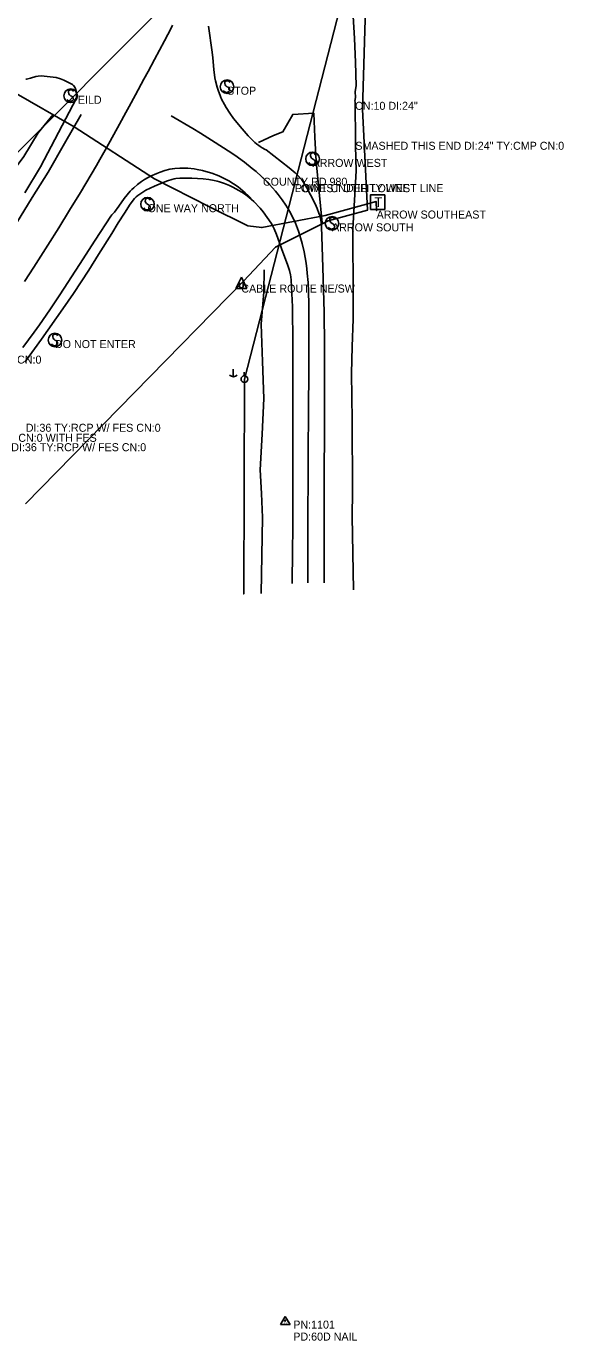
# Model space of a CAD drawing. Extents: x 1676038 to 1677961, y 226475 to 233854.
# Drawn here: x 1677207 to 1677543, y 227480 to 228301 of the extents above; entities that cross this region are included whole.
import ezdxf

# ---------------------------------------------------------------- set-up
doc = ezdxf.new("R2010")
doc.units = 0
for name, color, linetype in [('S_BASELINE', 7, 'Continuous'), ('S_CROSS_DRAIN_ANNOT', 7, 'Continuous'), ('S_DITCHLINE', 7, 'Continuous'), ('S_DRG_PT_SYM', 7, 'Continuous'), ('S_EDGE_PAVEMENT', 7, 'Continuous'), ('S_ELECTRIC_UTILITIES', 7, 'Continuous'), ('S_ELECTRIC_UTILITIES_ANNOT', 7, 'Continuous'), ('S_FIBER_OPTIC_CABLE', 7, 'Continuous'), ('S_FIBER_OPTIC_CABLE_ANNOT', 7, 'Continuous'), ('S_GRAVEL_ROAD', 7, 'Continuous'), ('S_MSC_PT_SYM', 7, 'Continuous'), ('S_PAVEMENT_CROWN', 7, 'Continuous'), ('S_SECONDARY_CTL', 7, 'Continuous'), ('S_SECONDARY_CTL_ANNOT', 7, 'Continuous'), ('S_SHOULDER', 7, 'Continuous'), ('S_SIDE_DRAIN', 7, 'Continuous'), ('S_SIDE_DRAIN_ANNOT', 7, 'Continuous'), ('S_SIGN', 7, 'Continuous'), ('S_SIGN_ANNOT', 7, 'Continuous'), ('S_SURVEY_TEXT_ANNOT', 7, 'Continuous'), ('S_TELEPHONE_UTILITIES', 7, 'Continuous'), ('S_UNDERGROUND_CABLE', 7, 'Continuous'), ('S_UTILITY_POLE', 7, 'Continuous'), ('S_UTILITY_POLE_ANNOT', 7, 'Continuous'), ('S_UTL_PT_SYM', 7, 'Continuous')]:
    doc.layers.add(name, color=color, linetype=linetype)

msp = doc.modelspace()

# ---------------------------------------------------------------- linework, layer by layer
at = {"layer": 'S_BASELINE'}
msp.add_line((1676625.89, 227646.73), (1677368.16, 228389.18), dxfattribs=at)
at = {"layer": 'S_DITCHLINE'}
for points in [[(1677412.24, 228254.17), (1677412.6, 228256.39), (1677412.47, 228260.11), (1677413, 228263.83), (1677412.54, 228278.59), (1677412.08, 228293.34), (1677411.18, 228307.32)], [(1677139.76, 228123.95), (1677153.43, 228142.29), (1677158.71, 228149.29), (1677171.09, 228169.75), (1677183.47, 228190.22), (1677194.37, 228204.93), (1677205.27, 228219.64), (1677214.14, 228234.4), (1677223.67, 228245.72)], [(1677411.34, 227948.81), (1677410.93, 227971.75), (1677410.52, 227994.7), (1677410.65, 228010.19), (1677410.77, 228025.67), (1677410.6, 228040.23), (1677410.43, 228054.8), (1677410.25, 228069.36), (1677410.08, 228083.92), (1677410.62, 228100.96), (1677411.16, 228118), (1677411.12, 228132.07), (1677411.08, 228146.13), (1677411.04, 228160.19), (1677411, 228174.26), (1677412.02, 228192.39), (1677413.03, 228210.53), (1677412.69, 228226.29), (1677412.54, 228228.6)], [(1677353.55, 227946.6), (1677353.97, 227970.29), (1677354.38, 227993.98), (1677353.74, 228008.93), (1677353.09, 228023.88), (1677354.22, 228046.14), (1677355.36, 228068.4), (1677354.45, 228091.59), (1677353.55, 228114.78), (1677355.39, 228135.08), (1677355.46, 228148.71)]]:
    msp.add_lwpolyline(points, dxfattribs=at)
at = {"layer": 'S_DRG_PT_SYM'}
for points in [[(1677412.36, 228253.75), (1677412.36, 228253.8), (1677412.36, 228253.75), (1677412.31, 228253.75), (1677412.36, 228253.75), (1677412.36, 228253.7), (1677412.36, 228253.75), (1677412.41, 228253.75)], [(1677412.53, 228228.77), (1677412.53, 228228.82), (1677412.53, 228228.77), (1677412.48, 228228.77), (1677412.53, 228228.77), (1677412.53, 228228.72), (1677412.53, 228228.77), (1677412.58, 228228.77)]]:
    msp.add_lwpolyline(points, dxfattribs=at)
at = {"layer": 'S_EDGE_PAVEMENT'}
for points in [[(1677393.01, 227953.24), (1677392.99, 227973.14), (1677393.01, 227986.86), (1677393.04, 228000.57), (1677393.07, 228014.29), (1677393.1, 228028), (1677393.16, 228041.08), (1677393.22, 228054.15), (1677393.28, 228067.22), (1677393.33, 228080.3), (1677393.16, 228101.3), (1677392.99, 228122.29), (1677392.57, 228136.22), (1677392.15, 228150.14), (1677391.79, 228163.04), (1677391.42, 228175.94), (1677391.24, 228178.28), (1677390.99, 228179.8), (1677390.25, 228182.79), (1677389.77, 228184.26), (1677388.64, 228187.15), (1677387.33, 228190), (1677384.48, 228195.62), (1677382.22, 228199.98), (1677381.02, 228202.09), (1677378.99, 228205.06), (1677376.64, 228207.74), (1677374.9, 228209.39), (1677371.13, 228212.53), (1677356.79, 228223.79), (1677356.22, 228224.05), (1677354.29, 228225.04), (1677353.07, 228225.78), (1677350.75, 228227.46), (1677349.65, 228228.37), (1677347.54, 228230.33), (1677345.53, 228232.42), (1677341.72, 228236.81), (1677336.42, 228243.33), (1677333.96, 228246.68), (1677331.69, 228250.16), (1677330.64, 228251.96), (1677328.85, 228255.49), (1677328.14, 228257.11), (1677327.27, 228259.3), (1677326.87, 228260.41), (1677326.06, 228262.94), (1677325.08, 228266.78), (1677324.71, 228268.72), (1677324.02, 228274.02), (1677323.4, 228281.16), (1677322.99, 228284.76), (1677320.78, 228300.93)], [(1677200.64, 228177.93), (1677210.53, 228193.87), (1677220.43, 228209.81), (1677230.72, 228227.78), (1677241.01, 228245.75)], [(1677204.51, 228100.23), (1677211.72, 228109.83), (1677215.01, 228114.43), (1677221.43, 228123.74), (1677227.68, 228133.17), (1677240.04, 228152.19), (1677249.84, 228167.22), (1677259.63, 228182.24), (1677260.35, 228183.07), (1677261.84, 228184.85), (1677264.58, 228188.49), (1677268.07, 228193.36), (1677269.86, 228195.7), (1677271.77, 228197.94), (1677272.79, 228199.01), (1677273.91, 228200.09), (1677276.31, 228202.13), (1677278.89, 228203.99), (1677280.68, 228205.14), (1677284.42, 228207.22), (1677288.37, 228209.05), (1677290.38, 228209.83), (1677293.46, 228210.84), (1677296.59, 228211.6), (1677298.18, 228211.89), (1677299.68, 228212.09), (1677302.7, 228212.33), (1677305.74, 228212.36), (1677307.76, 228212.26), (1677311.8, 228211.83), (1677313.55, 228211.55), (1677317.04, 228210.81), (1677320.46, 228209.87), (1677322.72, 228209.14), (1677327.14, 228207.42), (1677331.36, 228205.43), (1677333.41, 228204.32), (1677336.4, 228202.51), (1677339.26, 228200.52), (1677340.64, 228199.47), (1677343.56, 228196.97), (1677345.43, 228195.21), (1677349.05, 228191.52), (1677352.97, 228187.21), (1677354.84, 228184.98), (1677357.47, 228181.52), (1677359.81, 228177.9), (1677360.85, 228176.02), (1677361.69, 228174.31), (1677363.19, 228170.78), (1677367.12, 228159.82), (1677370.1, 228152.18), (1677371.35, 228148.32), (1677371.96, 228145.71), (1677372.17, 228144.39), (1677372.37, 228142.38), (1677373.23, 228125.66), (1677373.35, 228102.82), (1677373.48, 228079.98), (1677373.48, 228067.05), (1677373.48, 228054.12), (1677373.48, 228041.18), (1677373.48, 228028.25), (1677373.43, 228014.55), (1677373.39, 228000.85), (1677373.34, 227987.15), (1677373.29, 227973.45), (1677373.05, 227952.85)]]:
    msp.add_lwpolyline(points, dxfattribs=at)
at = {"layer": 'S_ELECTRIC_UTILITIES'}
for p, q in [((1677343.16, 228080.48), (1677425.49, 228399.8)), ((1677342.78, 227946.34), (1677343.16, 228080.48))]:
    msp.add_line(p, q, dxfattribs=at)
at = {"layer": 'S_FIBER_OPTIC_CABLE'}
for p, q in [((1677416.97, 228249.14), (1677419.05, 228321.79)), ((1677199.06, 228259.69), (1677236.65, 228238.11)), ((1677420.05, 228186.02), (1677416.97, 228249.14)), ((1677236.65, 228238.11), (1677286.95, 228205.7)), ((1677286.95, 228205.7), (1677321.23, 228188.13)), ((1677321.23, 228188.13), (1677345.29, 228176.33)), ((1677393.7, 228182.74), (1677425.52, 228191.41)), ((1677425.52, 228191.41), (1677425.83, 228185.81)), ((1677354.08, 228175.16), (1677393.7, 228182.74)), ((1677362.65, 228162.87), (1677395.47, 228179.35)), ((1677395.47, 228179.35), (1677420.05, 228186.02)), ((1677345.29, 228176.33), (1677354.08, 228175.16)), ((1677342.55, 228141.77), (1677362.65, 228162.87)), ((1677206.22, 228002.56), (1677342.55, 228141.77))]:
    msp.add_line(p, q, dxfattribs=at)
at = {"layer": 'S_GRAVEL_ROAD'}
msp.add_lwpolyline([(1677391.86, 228178.22), (1677389.92, 228197.38), (1677387.97, 228216.53), (1677387.22, 228231.6), (1677386.46, 228246.68), (1677373.41, 228245.91), (1677367.22, 228234.89), (1677361.37, 228232.62), (1677351.91, 228228.25)], dxfattribs=at)
at = {"layer": 'S_MSC_PT_SYM'}
for points in [[(1677354.75, 228206.33), (1677354.75, 228206.38), (1677354.75, 228206.33), (1677354.7, 228206.33), (1677354.75, 228206.33), (1677354.75, 228206.28), (1677354.75, 228206.33), (1677354.8, 228206.33)], [(1677374.72, 228202.29), (1677374.72, 228202.34), (1677374.72, 228202.29), (1677374.67, 228202.29), (1677374.72, 228202.29), (1677374.72, 228202.24), (1677374.72, 228202.29), (1677374.77, 228202.29)]]:
    msp.add_lwpolyline(points, dxfattribs=at)
at = {"layer": 'S_PAVEMENT_CROWN'}
for points in [[(1677205.64, 228141.43), (1677211.52, 228150.46), (1677220.23, 228164.08), (1677227.05, 228175.06), (1677233.86, 228186.03), (1677240.57, 228197.07), (1677247.35, 228208.36), (1677250.69, 228214.03), (1677252.78, 228217.67), (1677256.92, 228224.98), (1677265, 228239.68), (1677269, 228247.04), (1677270.99, 228250.71), (1677274.97, 228258.06), (1677280.3, 228267.86), (1677282.97, 228272.78), (1677287, 228280.19), (1677293.29, 228291.86), (1677295.33, 228295.75), (1677296.33, 228297.69), (1677298.28, 228301.57)], [(1677382.81, 227953.23), (1677382.74, 227973.42), (1677382.8, 227987.07), (1677382.87, 228000.72), (1677382.94, 228014.37), (1677383.01, 228028.03), (1677383.1, 228041.01), (1677383.19, 228053.99), (1677383.29, 228066.97), (1677383.38, 228079.96), (1677383.41, 228101.62), (1677383.44, 228123.28), (1677383.42, 228127.21), (1677383.25, 228135), (1677382.95, 228140.8), (1677382.48, 228146.58), (1677382.18, 228149.46), (1677381.72, 228152.98), (1677380.52, 228159.98), (1677379.34, 228165.18), (1677377.86, 228170.3), (1677377.01, 228172.83), (1677375.04, 228177.84), (1677373.54, 228181.1), (1677371.31, 228185.34), (1677370.1, 228187.4), (1677369.02, 228189.13), (1677366.71, 228192.52), (1677364.25, 228195.78), (1677362.53, 228197.9), (1677358.91, 228201.99), (1677357.28, 228203.69), (1677353.94, 228206.98), (1677350.46, 228210.13), (1677348.08, 228212.16), (1677343.18, 228216.04), (1677337.18, 228220.34), (1677333.09, 228223.09), (1677324.81, 228228.42), (1677315.63, 228234.2), (1677310.97, 228236.99), (1677297.32, 228244.96)]]:
    msp.add_lwpolyline(points, dxfattribs=at)
at = {"layer": 'S_SECONDARY_CTL'}
for p, q in [((1677368.72, 227494.85), (1677365.71, 227489.9)), ((1677365.71, 227489.9), (1677371.67, 227489.9)), ((1677368.72, 227494.85), (1677371.67, 227489.9))]:
    msp.add_line(p, q, dxfattribs=at)
for radius in [0.311, 0.183, 0.103]:
    msp.add_circle((1677368.72, 227492.24), radius, dxfattribs=at)
at = {"layer": 'S_SHOULDER'}
for points in [[(1677206.5, 228267.87), (1677206.98, 228267.95), (1677209.47, 228268.53), (1677212.66, 228269.48), (1677214.27, 228269.8), (1677216.11, 228269.91), (1677219.85, 228269.64), (1677223.57, 228269.19), (1677225.39, 228268.87), (1677228.09, 228268.14), (1677230.16, 228267.29), (1677234.08, 228265.32), (1677235.59, 228264.48), (1677236.26, 228263.96), (1677237.14, 228262.9), (1677237.6, 228261.94), (1677237.78, 228261.36), (1677238.01, 228260.36), (1677238.24, 228257.89), (1677238.29, 228255.7), (1677238.29, 228255.98), (1677238.29, 228256.03)], [(1677205.85, 228196.84), (1677215.64, 228213.05), (1677226.95, 228234.53), (1677238.26, 228256)], [(1677205.8, 228091.1), (1677216.32, 228105.47), (1677229.71, 228124.4), (1677236.26, 228133.97), (1677245.82, 228148.48), (1677252.02, 228158.3), (1677260.19, 228171.46), (1677264.29, 228178.03), (1677268.17, 228184.17), (1677268.6, 228184.84), (1677271.38, 228189.27), (1677272.87, 228191.4), (1677274.51, 228193.38), (1677275.4, 228194.29), (1677276.5, 228195.26), (1677278.91, 228196.97), (1677281.51, 228198.45), (1677287.02, 228201.04), (1677292.36, 228203.39), (1677295.05, 228204.41), (1677297.78, 228205.22), (1677299.17, 228205.53), (1677300.36, 228205.73), (1677302.79, 228205.99), (1677305.25, 228206.1), (1677310.22, 228206.01), (1677317.34, 228205.56), (1677320.86, 228205.13), (1677324.34, 228204.51), (1677326.07, 228204.11), (1677327.65, 228203.68), (1677330.78, 228202.66), (1677333.84, 228201.43), (1677335.84, 228200.5), (1677339.71, 228198.42), (1677342.61, 228196.59), (1677344.01, 228195.6), (1677346.07, 228194.04), (1677349.04, 228191.5)]]:
    msp.add_lwpolyline(points, dxfattribs=at)
at = {"layer": 'S_SIDE_DRAIN'}
msp.add_line((1677412.53, 228228.77), (1677412.36, 228253.75), dxfattribs=at)
at = {"layer": 'S_SIGN'}
for centre in [(1677234.55, 228257.53), (1677332.3, 228263.17), (1677385.77, 228218.09), (1677282.56, 228189.77), (1677397.95, 228177.81), (1677224.7, 228104.88)]:
    msp.add_circle(centre, 4.24, dxfattribs=at)
for centre, radius, start, end in [((1677234.67, 228259.69), 1.62, 16.52582, 156.89569), ((1677332.04, 228261.77), 2.17, 204.64102, 335.35898), ((1677333.46, 228265.42), 2.55, 167.11961, 241.98129), ((1677332.42, 228265.32), 1.62, 16.52582, 156.89569), ((1677331.6, 228260.89), 2.38, 358.65289, 73.70634), ((1677234.28, 228256.13), 2.17, 204.64102, 335.35898), ((1677235.71, 228259.79), 2.55, 167.11961, 241.98129), ((1677233.84, 228255.25), 2.38, 358.65289, 73.70634), ((1677386.94, 228220.35), 2.55, 167.11961, 241.98129), ((1677385.9, 228220.25), 1.62, 16.52582, 156.89569), ((1677385.51, 228216.69), 2.17, 204.64102, 335.35898), ((1677385.07, 228215.81), 2.38, 358.65289, 73.70634), ((1677282.3, 228188.37), 2.17, 204.64102, 335.35898), ((1677283.72, 228192.02), 2.55, 167.11961, 241.98129), ((1677282.68, 228191.92), 1.62, 16.52582, 156.89569), ((1677281.86, 228187.49), 2.38, 358.65289, 73.70634), ((1677399.12, 228180.06), 2.55, 167.11961, 241.98129), ((1677398.08, 228179.96), 1.62, 16.52582, 156.89569), ((1677397.69, 228176.41), 2.17, 204.64102, 335.35898), ((1677397.25, 228175.52), 2.38, 358.65289, 73.70634), ((1677225.87, 228107.14), 2.55, 167.11961, 241.98129), ((1677224.83, 228107.04), 1.62, 16.52582, 156.89569), ((1677224, 228102.6), 2.38, 358.65289, 73.70634), ((1677224.44, 228103.48), 2.17, 204.64102, 335.35898)]:
    msp.add_arc(centre, radius, start, end, dxfattribs=at)
at = {"layer": 'S_TELEPHONE_UTILITIES'}
msp.add_lwpolyline([(1677421.91, 228186.56), (1677421.91, 228195.56), (1677430.91, 228195.56), (1677430.91, 228186.56)], close=True, dxfattribs=at)
at = {"layer": 'S_UNDERGROUND_CABLE'}
for p, q in [((1677341.24, 228144.11), (1677337.71, 228137.02)), ((1677340.04, 228138.26), (1677340.04, 228140.7)), ((1677340.66, 228137.6), (1677340.04, 228138.26)), ((1677341.86, 228137.6), (1677340.66, 228137.6)), ((1677341.24, 228144.11), (1677344.73, 228137.02)), ((1677342.4, 228138.26), (1677341.86, 228137.6)), ((1677342.4, 228140.7), (1677342.4, 228138.26)), ((1677337.71, 228137.02), (1677344.73, 228137.02))]:
    msp.add_line(p, q, dxfattribs=at)
at = {"layer": 'S_UTILITY_POLE'}
for p, q in [((1677336.19, 228086.7), (1677336.19, 228081.97)), ((1677343.03, 228082.63), (1677343.03, 228084.74))]:
    msp.add_line(p, q, dxfattribs=at)
msp.add_circle((1677343.16, 228080.49), 2.13, dxfattribs=at)
msp.add_arc((1677336.25, 228085.4), 3.41, 226.39718, 313.60282, dxfattribs=at)
at = {"layer": 'S_UTL_PT_SYM'}
for points in [[(1677416.97, 228249.14), (1677416.97, 228249.19), (1677416.97, 228249.14), (1677416.92, 228249.14), (1677416.97, 228249.14), (1677416.97, 228249.09), (1677416.97, 228249.14), (1677417.02, 228249.14)], [(1677236.65, 228238.11), (1677236.65, 228238.16), (1677236.65, 228238.11), (1677236.6, 228238.11), (1677236.65, 228238.11), (1677236.65, 228238.06), (1677236.65, 228238.11), (1677236.7, 228238.11)], [(1677286.95, 228205.7), (1677286.95, 228205.75), (1677286.95, 228205.7), (1677286.9, 228205.7), (1677286.95, 228205.7), (1677286.95, 228205.65), (1677286.95, 228205.7), (1677287, 228205.7)], [(1677374.72, 228202.29), (1677374.72, 228202.34), (1677374.72, 228202.29), (1677374.67, 228202.29), (1677374.72, 228202.29), (1677374.72, 228202.24), (1677374.72, 228202.29), (1677374.77, 228202.29)], [(1677321.23, 228188.13), (1677321.23, 228188.18), (1677321.23, 228188.13), (1677321.18, 228188.13), (1677321.23, 228188.13), (1677321.23, 228188.08), (1677321.23, 228188.13), (1677321.28, 228188.13)], [(1677425.52, 228191.41), (1677425.52, 228191.46), (1677425.52, 228191.41), (1677425.47, 228191.41), (1677425.52, 228191.41), (1677425.52, 228191.36), (1677425.52, 228191.41), (1677425.57, 228191.41)], [(1677393.7, 228182.74), (1677393.7, 228182.79), (1677393.7, 228182.74), (1677393.65, 228182.74), (1677393.7, 228182.74), (1677393.7, 228182.69), (1677393.7, 228182.74), (1677393.75, 228182.74)], [(1677395.47, 228179.35), (1677395.47, 228179.4), (1677395.47, 228179.35), (1677395.42, 228179.35), (1677395.47, 228179.35), (1677395.47, 228179.3), (1677395.47, 228179.35), (1677395.52, 228179.35)], [(1677420.05, 228186.02), (1677420.05, 228186.07), (1677420.05, 228186.02), (1677420, 228186.02), (1677420.05, 228186.02), (1677420.05, 228185.97), (1677420.05, 228186.02), (1677420.1, 228186.02)], [(1677425.83, 228185.81), (1677425.83, 228185.86), (1677425.83, 228185.81), (1677425.78, 228185.81), (1677425.83, 228185.81), (1677425.83, 228185.76), (1677425.83, 228185.81), (1677425.88, 228185.81)], [(1677345.29, 228176.33), (1677345.29, 228176.38), (1677345.29, 228176.33), (1677345.24, 228176.33), (1677345.29, 228176.33), (1677345.29, 228176.28), (1677345.29, 228176.33), (1677345.34, 228176.33)], [(1677354.08, 228175.16), (1677354.08, 228175.21), (1677354.08, 228175.16), (1677354.03, 228175.16), (1677354.08, 228175.16), (1677354.08, 228175.11), (1677354.08, 228175.16), (1677354.13, 228175.16)], [(1677362.65, 228162.87), (1677362.65, 228162.92), (1677362.65, 228162.87), (1677362.6, 228162.87), (1677362.65, 228162.87), (1677362.65, 228162.82), (1677362.65, 228162.87), (1677362.7, 228162.87)], [(1677342.55, 228141.77), (1677342.55, 228141.82), (1677342.55, 228141.77), (1677342.5, 228141.77), (1677342.55, 228141.77), (1677342.55, 228141.72), (1677342.55, 228141.77), (1677342.6, 228141.77)], [(1677343.16, 228080.48), (1677343.16, 228080.53), (1677343.16, 228080.48), (1677343.11, 228080.48), (1677343.16, 228080.48), (1677343.16, 228080.43), (1677343.16, 228080.48), (1677343.21, 228080.48)], [(1677342.78, 227946.34), (1677342.78, 227946.39), (1677342.78, 227946.34), (1677342.73, 227946.34), (1677342.78, 227946.34), (1677342.78, 227946.29), (1677342.78, 227946.34), (1677342.83, 227946.34)]]:
    msp.add_lwpolyline(points, dxfattribs=at)

# ---------------------------------------------------------------- texts
at = {"layer": 'S_CROSS_DRAIN_ANNOT'}
for s, p in [('DI:36 TY:RCP W/ FES CN:0', (1677131.9, 228090.15)), ('DI:36 TY:RCP W/ FES CN:0', (1677206.45, 228047.59)), ('DI:36 TY:RCP W/ FES CN:0', (1677197.38, 228035.44)), ('CN:0 WITH FES', (1677201.77, 228041.3))]:
    msp.add_text(s, height=5, dxfattribs=at).set_placement(p)
at = {"layer": 'S_ELECTRIC_UTILITIES_ANNOT'}
msp.add_text('LOWEST UTILITY LINE', height=5, dxfattribs=at).set_placement((1677374.72, 228197.29))
at = {"layer": 'S_FIBER_OPTIC_CABLE_ANNOT'}
msp.add_text('ARROW SOUTHEAST', height=5, dxfattribs=at).set_placement((1677425.83, 228180.81))
at = {"layer": 'S_SECONDARY_CTL'}
msp.add_text('TV', height=1.5, rotation=360, dxfattribs=at).set_placement((1677367.52, 227490.23))
at = {"layer": 'S_SECONDARY_CTL_ANNOT'}
for s, p in [('PN:1101', (1677373.72, 227487.24)), ('PD:60D NAIL', (1677373.72, 227479.74))]:
    msp.add_text(s, height=5, dxfattribs=at).set_placement(p)
at = {"layer": 'S_SIDE_DRAIN_ANNOT'}
for s, p in [('CN:10 DI:24"', (1677412.36, 228248.75)), ('SMASHED THIS END DI:24" TY:CMP CN:0', (1677412.53, 228223.77))]:
    msp.add_text(s, height=5, dxfattribs=at).set_placement(p)
at = {"layer": 'S_SIGN_ANNOT'}
for s, p in [('STOP', (1677332.3, 228258.17)), ('YEILD', (1677234.55, 228252.53)), ('ARROW WEST', (1677385.77, 228213.09)), ('ONE WAY NORTH', (1677282.56, 228184.77)), ('ARROW SOUTH', (1677397.95, 228172.81)), ('DO NOT ENTER', (1677224.7, 228099.88))]:
    msp.add_text(s, height=5, dxfattribs=at).set_placement(p)
at = {"layer": 'S_SURVEY_TEXT_ANNOT'}
for s, p in [('COUNTY RD 980', (1677354.75, 228201.33)), ('POINT UNDER LOWEST LINE', (1677374.72, 228197.29))]:
    msp.add_text(s, height=5, dxfattribs=at).set_placement(p)
at = {"layer": 'S_TELEPHONE_UTILITIES'}
msp.add_text('T', height=6, rotation=360, dxfattribs=at).set_placement((1677424.47, 228188.06))
at = {"layer": 'S_UTILITY_POLE_ANNOT'}
msp.add_text('CABLE ROUTE NE/SW', height=5, dxfattribs=at).set_placement((1677341.24, 228134.58))

doc.saveas('drawing.dxf')
